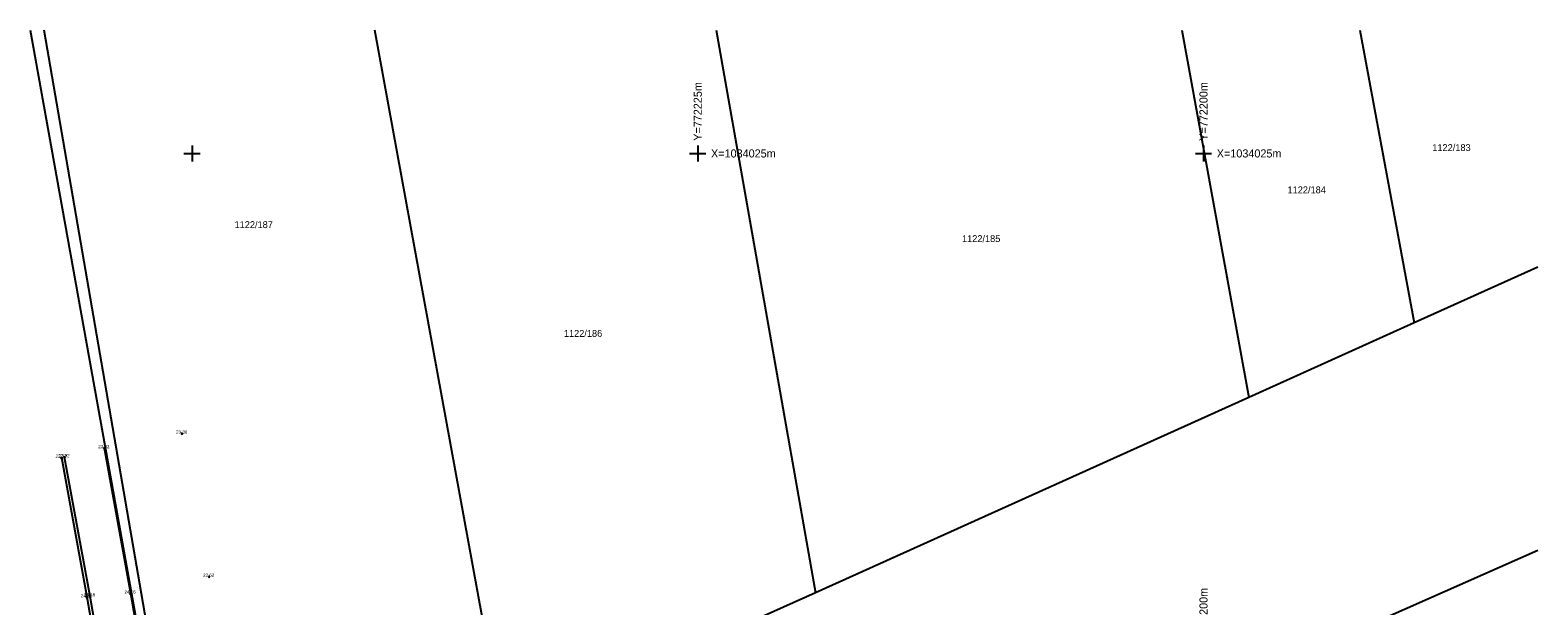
# Model space of a CAD drawing. Extents: x -772300 to -772183, y -1034101 to -1034019.
# Drawn here: x -772258 to -772183.5, y -1034047.4 to -1034018.9 of the extents above; entities that cross this region are included whole.
import ezdxf

# ---------------------------------------------------------------- set-up
doc = ezdxf.new("R2010")
doc.units = 0
for name, color, linetype in [('body', 7, 'Continuous'), ('KM_hranice', 7, 'Continuous'), ('KM_parcelni_cisla', 7, 'Continuous'), ('oddeleni_ploch', 7, 'Continuous'), ('souradnicova_sit', 7, 'Continuous'), ('vyskove_koty', 7, 'Continuous')]:
    doc.layers.add(name, color=color, linetype=linetype)

msp = doc.modelspace()

# ---------------------------------------------------------------- linework, layer by layer
at = {"layer": 'body'}
for p, q in [((-772250.44, -1034038.89), (-772250.52, -1034038.81)), ((-772250.52, -1034038.89), (-772250.44, -1034038.81)), ((-772254.29, -1034039.61), (-772254.37, -1034039.53)), ((-772254.37, -1034039.61), (-772254.29, -1034039.53)), ((-772256.4, -1034040.09), (-772256.48, -1034040.01)), ((-772256.48, -1034040.09), (-772256.4, -1034040.01)), ((-772256.26, -1034040.06), (-772256.34, -1034039.98)), ((-772256.34, -1034040.06), (-772256.26, -1034039.98)), ((-772249.11, -1034045.97), (-772249.19, -1034045.89)), ((-772249.19, -1034045.97), (-772249.11, -1034045.89)), ((-772255.15, -1034046.98), (-772255.23, -1034046.9)), ((-772255.23, -1034046.98), (-772255.15, -1034046.9)), ((-772255, -1034046.94), (-772255.08, -1034046.86)), ((-772255.08, -1034046.94), (-772255, -1034046.86)), ((-772252.99, -1034046.8), (-772253.07, -1034046.72)), ((-772253.07, -1034046.8), (-772252.99, -1034046.72))]:
    msp.add_line(p, q, dxfattribs=at)
at = {"layer": 'KM_hranice'}
for p, q in [((-772258.001, -1034018.905), (-772250.49, -1034060.71)), ((-772250.12, -1034060.55), (-772257.314, -1034018.905)), ((-772234.61, -1034053.62), (-772240.956, -1034018.905)), ((-772224.096, -1034018.905), (-772219.18, -1034046.72)), ((-772201.077, -1034018.905), (-772197.76, -1034037.07)), ((-772192.265, -1034018.905), (-772189.58, -1034033.38)), ((-772183.472, -1034030.627), (-772189.58, -1034033.38)), ((-772189.58, -1034033.38), (-772197.76, -1034037.07)), ((-772197.76, -1034037.07), (-772219.18, -1034046.72)), ((-772183.472, -1034044.635), (-772237.52, -1034068.47)), ((-772219.18, -1034046.72), (-772234.61, -1034053.62))]:
    msp.add_line(p, q, dxfattribs=at)
at = {"layer": 'oddeleni_ploch'}
for points in [[(-772251.7, -1034054.36), (-772253.03, -1034046.76), (-772254.33, -1034039.57)], [(-772253.82, -1034054.81), (-772255.19, -1034046.94), (-772256.44, -1034040.05)], [(-772253.67, -1034054.78), (-772255.04, -1034046.9), (-772256.3, -1034040.02)]]:
    msp.add_lwpolyline(points, dxfattribs=at)
at = {"layer": 'souradnicova_sit'}
for p, q in [((-772250, -1034024.6), (-772250, -1034025.4)), ((-772225, -1034024.6), (-772225, -1034025.4)), ((-772200, -1034024.6), (-772200, -1034025.4)), ((-772250.4, -1034025), (-772249.6, -1034025)), ((-772225.4, -1034025), (-772224.6, -1034025)), ((-772200.4, -1034025), (-772199.6, -1034025))]:
    msp.add_line(p, q, dxfattribs=at)

# ---------------------------------------------------------------- texts
at = {"layer": 'KM_parcelni_cisla'}
for s, p in [('1122/183', (-772188.69, -1034024.882)), ('1122/184', (-772195.847, -1034026.971)), ('1122/187', (-772247.898, -1034028.69)), ('1122/185', (-772211.939, -1034029.382)), ('1122/186', (-772231.619, -1034034.067))]:
    msp.add_text(s, height=0.34, dxfattribs=at).set_placement(p)
at = {"layer": 'souradnicova_sit'}
for s, p in [('Y=772225m', (-772224.8, -1034024.375)), ('Y=772200m', (-772199.8, -1034024.375)), ('Y=772200m', (-772199.8, -1034049.375))]:
    msp.add_text(s, height=0.4, rotation=90.01167, dxfattribs=at).set_placement(p)
for p in [(-772224.344, -1034025.2), (-772199.344, -1034025.2)]:
    msp.add_text('X=1034025m', height=0.4, dxfattribs=at).set_placement(p)
at = {"layer": 'vyskove_koty'}
for s, p in [('23.36', (-772250.785, -1034038.85)), ('23.92', (-772256.605, -1034040.02)), ('23.92', (-772254.635, -1034039.57)), ('23.77', (-772256.745, -1034040.05)), ('23.62', (-772249.455, -1034045.93)), ('24.02', (-772255.495, -1034046.94)), ('24.18', (-772255.345, -1034046.9)), ('24.16', (-772253.335, -1034046.76))]:
    msp.add_text(s, height=0.16, dxfattribs=at).set_placement(p)

doc.saveas('drawing.dxf')
